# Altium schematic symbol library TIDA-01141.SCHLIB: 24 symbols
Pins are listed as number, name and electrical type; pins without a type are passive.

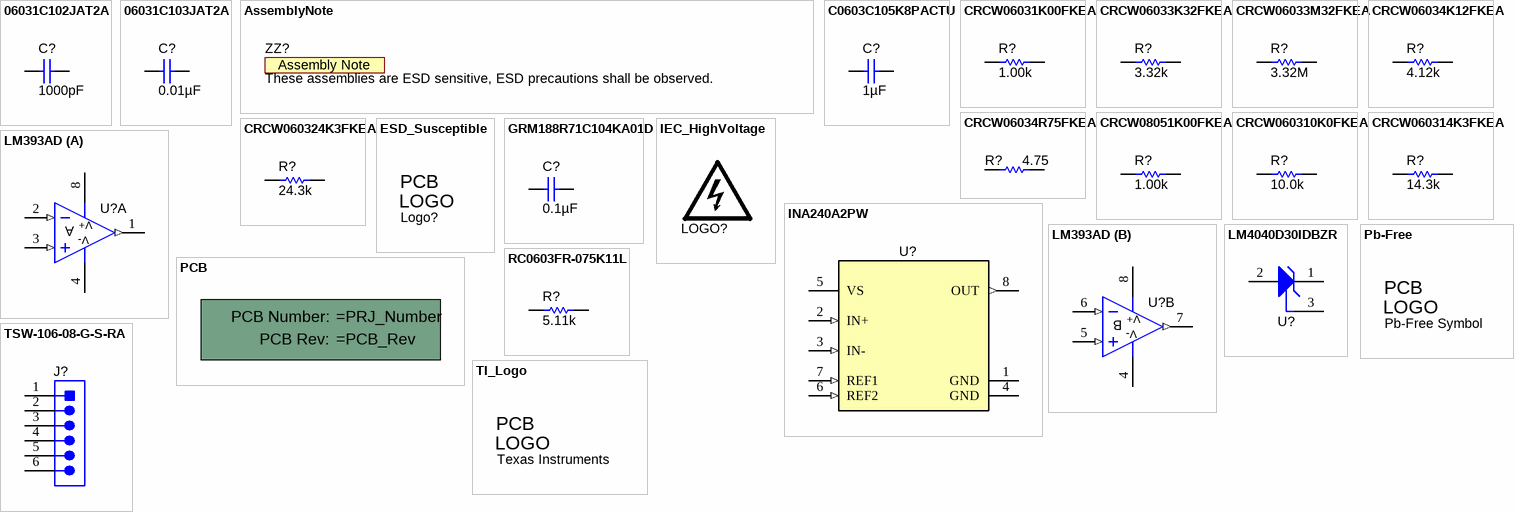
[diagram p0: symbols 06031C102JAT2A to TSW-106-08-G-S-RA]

## 06031C102JAT2A
designator C?  ValueDisplayed: 1000pF  (hidden comment: 06031C102JAT2A)
CAP, CERM, 1000 pF, 100 V, +/- 5%, X7R, 0603; Manufacturer: AVX; Polarized: N; CompType: Capacitor; Value: 1000pF; U/M: EA; Cap_F: 0.000000001; Tolerance_%: 5; ESR_ohm: 0.276; Value1: 0.276 ohm; VDC_V: 100; Value2: 100V; TaMin_C: -55; TaMax_C: 125; Cap_Case: 0603; SizeArea_mm2: 1.28; SizeAreaWB_mm2: 4.68; SizeX_mm: 1.6; SizeY_mm: 0.8; SizeZ_mm: 1; AEC Category: Q200
signal-integrity model Cap
simulation model Cap
footprint 0603
footprint 0603M
footprint 0603L
footprint 0603_HV
footprint 0603S
pins: 1, 2

## 06031C103JAT2A
designator C?  ValueDisplayed: 0.01µF  (hidden comment: 06031C103JAT2A)
CAP, CERM, 0.01 µF, 100 V, +/- 5%, X7R, 0603; Manufacturer: AVX; Polarized: N; CompType: Capacitor; Value: 0.01uF; U/M: EA; Cap_F: 0.00000001; Tolerance_%: 5; ESR_ohm: 0.098; Value1: 0.098 ohm; VDC_V: 100; Value2: 100V; TaMin_C: -55; TaMax_C: 125; Cap_Case: 0603
signal-integrity model Cap
simulation model Cap
footprint 0603
footprint 0603M
footprint 0603L
footprint 0603_HV
footprint 0603S
pins: 1, 2

## AssemblyNote
designator ZZ?, comment These assemblies are ESD sensitive, ESD precautions shall be observed.  (no BOM)
SymbolCreator: codlsc; CompType: AssemblyNote
footprint AssemblyNote

## C0603C105K8PACTU
designator C?  ValueDisplayed: 1µF  (hidden comment: C0603C105K8PACTU)
CAP, CERM, 1 µF, 10 V, +/- 10%, X5R, 0603; Manufacturer: Kemet; Polarized: N; CompType: Capacitor; Value: 1uF; U/M: EA; Cap_F: 0.000001; Tolerance_%: 10; Value1: Unknown; Value2: 10V; TaMin_C: -55; TaMax_C: 85; Cap_Case: 0603
signal-integrity model Cap
simulation model Cap
footprint 0603
footprint 0603M
footprint 0603L
footprint 0603_HV
footprint 0603S
pins: 1, 2

## CRCW06031K00FKEA
designator R?  ValueDisplayed: 1.00k  (hidden comment: CRCW06031K00FKEA)
RES, 1.00 k, 1%, 0.1 W, 0603; Manufacturer: Vishay-Dale; CompType: Resistor; Value: 1.00k; Res_ohm: 1000; Value_Code: 1k00; Tolerance_%: 1; Power_W: 0.1; Value2: 0.1W; VDC_V: 75; TempCo: 100 ppm/C; SizeArea_mm2: 1.28; SizeX_mm: 1.6; SizeY_mm: 0.8; EIA_Code: E96; U/M: EA; AEC Category: Q200
signal-integrity model Resistor
simulation model Resistor
footprint 0603
footprint 0603M
footprint 0603L
footprint 0603_HV
footprint 0603S
pins: 1, 2

## CRCW06033K32FKEA
designator R?  ValueDisplayed: 3.32k  (hidden comment: CRCW06033K32FKEA)
RES, 3.32 k, 1%, 0.1 W, 0603; Manufacturer: Vishay-Dale; CompType: Resistor; Value: 3.32k; Res_ohm: 3320; Value_Code: 3k32; Tolerance_%: 1; Power_W: 0.1; Value2: 0.1W; VDC_V: 75; TempCo: 100 ppm/C; EIA_Code: E96; U/M: EA
signal-integrity model Resistor
simulation model Resistor
footprint 0603
footprint 0603M
footprint 0603L
footprint 0603_HV
footprint 0603S
pins: 1, 2

## CRCW06033M32FKEA
designator R?  ValueDisplayed: 3.32M  (hidden comment: CRCW06033M32FKEA)
RES, 3.32 M, 1%, 0.1 W, 0603; Manufacturer: Vishay-Dale; CompType: Resistor; Value: 3.32Meg; Res_ohm: 3320000; Value_Code: 3M32; Tolerance_%: 1; Power_W: 0.1; Value2: 0.1W; VDC_V: 75; TempCo: 100 ppm/C; EIA_Code: E96; U/M: EA
signal-integrity model Resistor
simulation model Resistor
footprint 0603
footprint 0603M
footprint 0603L
footprint 0603_HV
footprint 0603S
pins: 1, 2

## CRCW06034K12FKEA
designator R?  ValueDisplayed: 4.12k  (hidden comment: CRCW06034K12FKEA)
RES, 4.12 k, 1%, 0.1 W, 0603; Manufacturer: Vishay-Dale; CompType: Resistor; Value: 4.12k; Res_ohm: 4120; Value_Code: 4k12; Tolerance_%: 1; Power_W: 0.1; Value2: 0.1W; VDC_V: 75; TempCo: 100 ppm/C; EIA_Code: E96; U/M: EA
signal-integrity model Resistor
simulation model Resistor
footprint 0603
footprint 0603M
footprint 0603L
footprint 0603_HV
footprint 0603S
pins: 1, 2

## CRCW06034R75FKEA
designator R?  ValueDisplayed: 4.75  (hidden comment: CRCW06034R75FKEA)
RES, 4.75, 1%, 0.1 W, 0603; Manufacturer: Vishay-Dale; CompType: Resistor; Value: 4.75; Value_Code: 4R75; Tolerance_%: 1; Power_W: 0.1; Value2: 0.1W; VDC_V: 75; TempCo: 100 ppm/C; EIA_Code: E96; U/M: EA
signal-integrity model Resistor
simulation model Resistor
footprint 0603
footprint 0603M
footprint 0603L
footprint 0603_HV
footprint 0603S
pins: 1, 2

## CRCW08051K00FKEA
designator R?  ValueDisplayed: 1.00k  (hidden comment: CRCW08051K00FKEA)
RES, 1.00 k, 1%, 0.125 W, 0805; Manufacturer: Vishay-Dale; CompType: Resistor; Value: 1.00k; Res_ohm: 1000; Value_Code: 1k00; Tolerance_%: 1; Power_W: 0.125; Value2: 0.125W; VDC_V: 150; TempCo: 100 ppm/C; EIA_Code: E96; U/M: EA; AEC Category: Q200
signal-integrity model Resistor
simulation model Resistor
footprint 0805_HV
footprint 0805_HV1
footprint 0805
footprint 0805M
pins: 1, 2

## CRCW060310K0FKEA
designator R?  ValueDisplayed: 10.0k  (hidden comment: CRCW060310K0FKEA)
RES, 10.0 k, 1%, 0.1 W, 0603; Manufacturer: Vishay-Dale; CompType: Resistor; Value: 10.0k; Res_ohm: 10000; Value_Code: 10k0; Tolerance_%: 1; Power_W: 0.1; Value2: 0.1W; VDC_V: 75; TempCo: 100 ppm/C; EIA_Code: E96; U/M: EA
signal-integrity model Resistor
simulation model Resistor
footprint 0603
footprint 0603M
footprint 0603L
footprint 0603_HV
footprint 0603S
pins: 1, 2

## CRCW060314K3FKEA
designator R?  ValueDisplayed: 14.3k  (hidden comment: CRCW060314K3FKEA)
RES, 14.3 k, 1%, 0.1 W, 0603; Manufacturer: Vishay-Dale; CompType: Resistor; Value: 14.3k; Res_ohm: 14300; Value_Code: 14k3; Tolerance_%: 1; Power_W: 0.1; Value2: 0.1W; VDC_V: 75; TempCo: 100 ppm/C; EIA_Code: E96; U/M: EA
signal-integrity model Resistor
simulation model Resistor
footprint 0603
footprint 0603M
footprint 0603L
footprint 0603_HV
footprint 0603S
pins: 1, 2

## CRCW060324K3FKEA
designator R?  ValueDisplayed: 24.3k  (hidden comment: CRCW060324K3FKEA)
RES, 24.3 k, 1%, 0.1 W, 0603; Manufacturer: Vishay-Dale; CompType: Resistor; Value: 24.3k; Res_ohm: 24300; Value_Code: 24k3; Tolerance_%: 1; Power_W: 0.1; Value2: 0.1W; VDC_V: 75; TempCo: 100 ppm/C; EIA_Code: E96; U/M: EA
signal-integrity model Resistor
simulation model Resistor
footprint 0603
footprint 0603M
footprint 0603L
footprint 0603_HV
footprint 0603S
pins: 1, 2

## ESD_Susceptible
designator Logo?, comment ESD Susceptible  (value not drawn)  (no BOM)
ESD Susceptible Symbol; SymbolCreator: a0412235
footprint ESD_Overlay_Large
footprint ESD_Overlay_Medium
footprint ESD_Overlay_Small

## GRM188R71C104KA01D
designator C?  ValueDisplayed: 0.1µF  (hidden comment: GRM188R71C104KA01D)
CAP, CERM, 0.1 µF, 16 V, +/- 10%, X7R, 0603; Manufacturer: MuRata; Polarized: N; CompType: Capacitor; Value: 0.1uF; U/M: EA; Cap_F: 0.0000001; Tolerance_%: 10; Value1: Unknown; VDC_V: 16; Value2: 16V; TaMin_C: -55; TaMax_C: 125; Cap_Case: 0603; SizeArea_mm2: 1.28; SizeAreaWB_mm2: 4.68; SizeX_mm: 1.6; SizeY_mm: 0.8; SizeZ_mm: 1; AEC Category: Q200
signal-integrity model Cap
simulation model Cap
footprint 0603
footprint 0603M
footprint 0603L
footprint 0603_HV
footprint 0603S
pins: 1, 2

## IEC_HighVoltage
designator LOGO?, comment DANGER HIGH VOLTAGE  (value not drawn)  (no BOM)
IEC 61010-1 High Voltage Warning; SymbolCreator: a0412235
footprint IEC_HighVoltage_Large
footprint IEC_HighVoltage_Medium
footprint IEC_HighVoltage_Small

## INA240A2PW
designator U?  (value not drawn)
Wide Common-Mode Range, Voltage Output, High or Low-Side Bi-Directional Zero-Drift Current Shunt Monitor, PW0008A; Manufacturer: Texas Instruments; SymbolCreator: Altium; SizeArea_mm2: 19.2; SizeAreaWB_mm2: 42; SizeX_mm: 6.4; SizeY_mm: 3; SizeZ_mm: 1.2; CompType: IC; U/M: EA
footprint PW0008A_N
footprint PW0008A_M
footprint PW0008A_L
pins: 1 GND (power), 2 IN+ (in), 3 IN- (in), 4 GND (power), 5 VS (power), 6 REF2 (in), 7 REF1 (in), 8 OUT (out)

## LM393AD
designator U?  (value not drawn)
Dual Comparator, D0008A; Manufacturer: Texas Instruments; CompType: OpAmp IC
footprint D0008A_N
footprint D0008A_M
footprint D0008A_L
simulation model LM393A (SUBCKT)
pins on every part: 4 V- (power), 8 V+ (power)
part A pins: 1 OUT (out), 2 IN- (in), 3 IN+ (in)
part B pins: 5 IN+ (in), 6 IN- (in), 7 OUT (out)
1 alternate drawing of the same symbol

## LM4040D30IDBZR
designator U?  (value not drawn)
Precision Micropower Shunt Voltage Reference, 1% accuracy, 3 V, 15 ppm / degC, 15 mA, -40 to 85 degC, 3-pin SOT-23 (DBZ), Green (RoHS & no Sb/Br); Manufacturer: Texas Instruments; Alternate PartNumber: Equivalent; Initial Accuracy @ 25/deg C(%): 1; Iout/Iz(Max)(mA): 15; Min Iz for Regulation(uA): 65; Rating: Catalog; Temp Coeff(Max)(ppm/ degree C): 150; VO(V): 3
footprint DBZ0003A_N (SOT23, 3-Leads, Body 2.92x1.3 mm, Pitch 0.95 mm, IPC Medium Density)
footprint DBZ0003A_L (SOT23, 3-Leads, Body 2.92x1.3 mm, Pitch 0.95 mm, IPC High Density)
footprint DBZ0003A_M (SOT23, 3-Leads, Body 2.92x1.3 mm, Pitch 0.95 mm, IPC Low Density)
pins: 1 CATHODE, 2 ANODE, 3 NC

## Pb-Free
designator Logo?, comment Pb-Free Symbol  (no BOM)
SymbolCreator: a0412235
footprint Pb-Free_Overlay_Medium
footprint Pb-Free_Overlay_Small

## PCB
designator !PCB?, comment Printed Circuit Board  (value not drawn)  (mechanical)
Manufacturer: Any; SymbolCreator: a0412235; CompType: PCB
1 alternate drawing of the same symbol

## RC0603FR-075K11L
designator R?  ValueDisplayed: 5.11k  (hidden comment: RC0603FR-075K11L)
RES, 5.11 k, 1%, 0.1 W, 0603; Manufacturer: Yageo America; CompType: Resistor; Value: 5.11k; Res_ohm: 5110; Value_Code: 5k11; Tolerance_%: 1; Power_W: 0.1; Value2: 0.1W; VDC_V: 150; TempCo: 200 ppm/C; EIA_Code: E96; U/M: EA
signal-integrity model Resistor
simulation model Resistor
footprint 0603
footprint 0603M
footprint 0603L
footprint 0603_HV
footprint 0603S
pins: 1, 2

## TI_Logo
designator Logo?, comment Texas Instruments  (no BOM)
Texas Instrument Corporate Signature; SymbolCreator: codlsc
footprint TI_Stacked_SolderMask_Medium
footprint TI_Stacked_SolderMask_Small
footprint TI_Stacked_Overlay_Medium
footprint TI_Stacked_Overlay_Small
footprint TI_Horizontal_SolderMask_Medium
footprint TI_Horizontal_SolderMask_Small
footprint TI_Horizontal_Overlay_Medium
footprint TI_Horizontal_Overlay_Small
footprint TI_Symbol_SolderMask_Small
footprint TI_Symbol_Overlay_Medium
footprint TI_Symbol_Overlay_Small
footprint TI_Symbol_SolderMask_Medium

## TSW-106-08-G-S-RA
designator J?  (value not drawn)
Header, 100mil, 6x1, Gold, R/A, TH; Manufacturer: Samtec; SymbolCreator: a0412235; Pitch_mm: 2.54; Gender: Male; Shrouded: N; Row_Count: 1; Current_A: 6.3; Voltage_V: 550; Cert_CSA: Y
footprint TSW-106-08-G-S-RA
pins: 1, 2, 3, 4, 5, 6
